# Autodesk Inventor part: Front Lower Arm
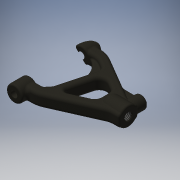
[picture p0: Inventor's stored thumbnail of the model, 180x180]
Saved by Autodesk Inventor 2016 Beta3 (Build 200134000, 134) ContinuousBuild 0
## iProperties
Shininess: 41.0
Compacted: True
Length Units: 11272
Angle Units: 11279
Time Units: 11290
Mass Units: 11286
Length Display Precision: 3
Angle Display Precision: 2
Company: Autodesk
Created: 2001-02
Part Number: Front Lower Arm
Document SubType Name: Modeling
Designer: Autodesk, Inc.
Project: Inventor Samples
Density: 1.28 g/cm^3
Mass: 4.8425 g
Surface Area: 27.2674 cm^2
Volume: 3.7832 cm^3
Material: Stiffzel
Appearance: Stiffzel
Density: 0.0
Volumn: 0.0
Area: 0.0
PropertySet Name: Model Information
Control State: 0
Master: False
Checked Out: False
Author: Autodesk, Inc.
Revision Number: A
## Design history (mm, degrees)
sketch "Sketch1"
  geometry: C1 r 4.001 at (-10.325, -2.008)
  constraints: 1 centre point
  dimensions: "d0" = 8.001 diameter of C1
extrude "Extrusion1" new body sketch "Sketch1" distance "d1" = 8.001 (= d0); taper "d2" = 0 deg
workaxis "Work Axis2"
workplane "Work Plane1"
sketch "Sketch2"
  geometry: C1 r 4.001 at (0, 0) reference
extrude "Extrusion2" join sketch "Sketch2" distance "d4" = 8.001 (= d1); taper "d5" = 0 deg
workplane "Work Plane2"
sketch "Sketch3"
  geometry: L1 (-35.418, -10.846)-(5.38, -10.846); L2 (-38.1, -6.083)-(-25.4, -6.083); L3 (-25.4, -6.083)-(-25.4, -15.608); L4 (-25.4, -15.608)-(-38.1, -15.608); L5 (-38.1, -15.608)-(-38.1, -6.083); L6 (-4.001, 8.001)-(4.001, 8.001) reference; L7 (0, -41.681)-(0, 16.281) reference; L8 (-4.001, 0)-(4.001, 0) reference; L9 (4.001, -25.4)-(-4.001, -25.4) reference; L10 (4.001, -33.401)-(-4.001, -33.401) reference; L11 (0, 0)-(0, 5.08); L12 (0, 5.08)-(-8.001, 5.08); L13 (0, 0)-(-8.001, 0); L14 (0, -25.4)-(-8.001, -25.4); L15 (0, -30.48)-(-8.001, -30.48); L16 (-8.001, 5.08)-(-33.338, -6.083); L17 (-33.338, -15.608)-(-8.001, -30.48); L18 (-8.001, 0)-(-25.4, -7.666); L19 (-25.4, -15.187)-(-8.001, -25.4); L20 (0, -25.4)-(0, -30.48); L21 (-8.001, 0)-(-13.882, -21.948); L22 (-12.473, -1.971)-(-17.29, -19.947)
  constraints: 34 end point, 12 parallel, 9 point on line, 3 perpendicular, 2 midpoint, 1 collinear, 1 horizontal, 1 vertical alignment
  dimensions: "d10" = 18.8468 distance between parallel lines of L6 L1; "d11" = 38.1 distance between parallel lines of L7 L5; "d12" = 9.525 distance of L4.end L2.start; "d13" = 4.7625 distance between parallel lines of L2 L1 (= 0.5 x d12); "d14" = 12.7 distance of L3.end L4.end; "d15" = 5.08 distance between parallel lines of L15 L14; "d16" = 5.08 distance between parallel lines of L13 L12 (= d15); "d17" = 8.001 distance of L11.end L12.end; "d18" = 4.7625 distance from line of L5 L17.start; "d26" = 3.81 distance between parallel lines of L21 L22; "d27" = 105 deg angle of L13 L21
extrude "Extrusion3" join sketch "Sketch3" stored distance "d20" = 6.35; taper "d21" = 0 deg
fillet "Fillet1" dims "d22" = 8.001
fillet "Fillet3" dims "d24" = 12.7
fillet "Fillet5" dims "d28" = 1.5875
fillet "Fillet6" dims "d29" = 1.5875
fillet "Fillet7" dims "d30" = 8.001
fillet "Fillet8" dims "d31" = 3.175, "d32" = 1.5875
fillet "Fillet9" dims "d33" = 1.5875
fillet "Fillet10" dims "d34" = 0.8128
fillet "Fillet11" dims "d35" = 1.5875
sketch "Sketch4"
  geometry: L1 (-8.632, -2.353)-(-13.256, -19.612) reference; L2 (-2.764, -25.4)-(-5.826, -25.4) reference; A1 r 12.413 centre (1.046, -14.195) between (-10.944, -10.983) and (-4.295, -25.4)
  constraints: 2 midpoint, 2 point on circle, 1 centre point, 1 tangent
feature "Rib1" sketch "Sketch4" dims "d37" = 2.54, "d38" = 2.54
fillet "Fillet13" dims "d39" = 0.8128
fillet "Fillet14" dims "d40" = 0.8128
sketch "Sketch5"
  geometry: L1 (-4.01, -0.325)-(-9.479, -7.009)
  constraints: 2 end point
feature "Rib2" sketch "Sketch5" dims "d41" = 2.54, "d42" = 2.54
fillet "Fillet15" dims "d43" = 0.8128
fillet "Fillet16" dims "d44" = 0.8128
sketch "Sketch6"
  geometry: L1 (-1.587, 0)-(-7.937, 3.175); C1 r 4.763 at (-4.762, 1.587); A1 r 1.587 centre (-1.587, 0) between (-1.587, -1.587) and (0, 0) reference; A2 r 1.587 centre (-7.937, 3.175) between (-7.937, 4.762) and (-9.525, 3.175) reference
  constraints: 2 end point, 1 centre point, 1 midpoint
  dimensions: "d45" = 9.525 diameter of C1
extrude "Extrusion4" join sketch "Sketch6" distance "d46" = 9.8425; taper "d47" = 0 deg
fillet "Fillet17" dims "d48" = 0.8128
fillet "Fillet18" dims "d49" = 0.8128
fillet "Fillet19" dims "d50" = 0.8128
workplane "Work Plane3"
sketch "Sketch7"
  geometry: C1 r 3.188 at (0, 0) reference; C2 r 1.587 at (0, 0)
  constraints: 1 centre point, 1 coincident
  dimensions: "d52" = 3.175 diameter of C2
extrude "Extrusion5" cut sketch "Sketch7" stored distance "d53" = 8.001; taper "d54" = 0 deg
sketch "Sketch8"
  geometry: L1 (-11.008, 1.587)-(47.933, 1.587) reference; L2 (-2.588, 3.175)-(-2.588, 0) reference; C1 r 3.175 at (0.841, 1.587)
  constraints: 1 centre point, 1 point on line
  dimensions: "d55" = 6.35 diameter of C1; "d56" = 3.429 distance from line of L2 C1.centre
extrude "Extrusion6" join sketch "Sketch8" stored distance "d57" = 8.001; taper "d58" = 0 deg
fillet "Fillet20" dims "d59" = 0.381
sketch "Sketch9"
  geometry: L1 (0, 0)-(8.496, 0); C1 r 3.175 at (0, 0) reference
  constraints: 2 end point, 1 horizontal
feature "Rib3" sketch "Sketch9" dims "d60" = 2.54, "d61" = 2.54
fillet "Fillet22" dims "d63" = 0.3556
fillet "Fillet23" dims "d64" = 0.8128
fillet "Fillet24" dims "d65" = 0.8128
sketch "Sketch10"
  geometry: A1 r 2.362 centre (0.841, 1.587) between (2.938, 2.675) and (2.938, 0.5) reference
hole "Hole1" sketch "Sketch10" at (0.841, 1.587) diameter "d66" = 2.159; stored, may be unused: countersink angle "d70" = 60 deg, drill point angle "d72" = 118 deg; dims "d67" = 12.7, "d68" = 9.525, "d69" = 6.35, "d71" = 6.35
fillet "Fillet25" dims "d73" = 0.3556
fillet "Fillet26" dims "d74" = 0.3556
sketch "Sketch11"
  geometry: A1 r 3.95 centre (0, 0) between (3.395, 2.019) and (2.967, -2.607); A2 r 3.95 centre (0, 0) between (2.879, 2.704) and (-2.879, 2.704) reference
  constraints: 2 concentric, 2 point on circle, 1 centre point
hole "Hole2" sketch "Sketch11" at (0, 0) diameter "d81" = 3.4036; stored, may be unused: drill point angle "d76" = 118 deg, countersink angle "d77" = 60 deg; dims "d75" = 12.7, "d78" = 6.35, "d79" = 9.525, "d80" = 9.525
chamfer "Chamfer1" distance "d82" = 0.381; stored, may be unused: second distance "d83" = 0.381, angle "d84" = 45 deg
body "Solid1"
other parameters: "d3" = 25.4, "d8" = 0, "d9" = 0, "d51" = 5.08
